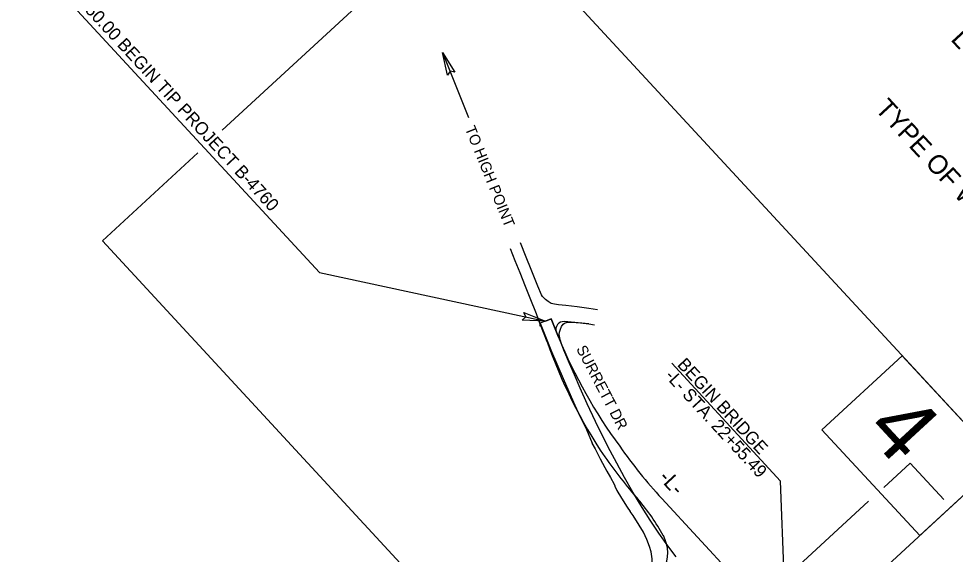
# Model space of a CAD drawing. Extents: x 1695041 to 1706254, y 786537 to 798223.
# Drawn here: x 1701995 to 1703837, y 795222 to 796276 of the extents above; entities that cross this region are included whole.
import ezdxf

# ---------------------------------------------------------------- set-up
doc = ezdxf.new("R2010")
doc.units = 0
for name, color, linetype in [('Default', 7, 'Continuous'), ('Old_Level_1', 7, 'Continuous'), ('Old_Level_3', 7, 'Continuous'), ('Old_Level_47', 7, 'Continuous'), ('Prop EOT', 7, 'Continuous'), ('Prop Terminator CELL', 7, 'Continuous'), ('Sheet Data Field CELL', 7, 'Continuous'), ('Sheet Title CELL', 7, 'Continuous')]:
    doc.layers.add(name, color=color, linetype=linetype)

msp = doc.modelspace()

# ---------------------------------------------------------------- linework, layer by layer
at = {"layer": 'Default'}
for p, q in [((1703042.2, 795685.9), (1703031.1, 795681.4)), ((1703052.8, 795659.7), (1703042.2, 795685.9)), ((1703031.1, 795681.4), (1703020, 795676.9)), ((1703020, 795676.9), (1703034.3, 795640.3)), ((1703056.9, 795649.4), (1703052.8, 795659.7)), ((1703279.5, 795598.4), (1703493.6, 795366.4)), ((1703449.8, 795126.4), (1703259.9, 795332.1))]:
    msp.add_line(p, q, dxfattribs=at)
for points in [[(1702347.2, 796012.7), (1702159.6, 795839.5), (1703188.6, 794724.8), (1703925.1, 795404.6), (1702896.1, 796519.3), (1702395.5, 796057.2)], [(1703147.7, 795414.2), (1703147.7, 795414.2)], [(1703814.8, 795329.9), (1703748.3, 795401.9), (1703696.3, 795353.9)], [(1703666.7, 795326.6), (1703127, 794828.4)]]:
    msp.add_lwpolyline(points, dxfattribs=at)
msp.add_lwpolyline([(1703925.1, 795404.6), (1703732.6, 795613), (1703574.9, 795467.4), (1703767.3, 795259)], close=True, dxfattribs=at)
for centre, radius, start, end in [((1703979, 796025.2), 995.7, 202.1738, 216.3622), ((1703995.4, 795980.9), 1019.7, 199.5127, 213.7658), ((1703981.5, 795998.2), 982, 215.0107, 222.7091), ((1703981.5, 795998.2), 1018, 215.0107, 221.0304), ((1702911.8, 795067.4), 400, 28.6224, 41.0304), ((1703201.5, 795225.4), 70, 332.0106, 28.6224)]:
    msp.add_arc(centre, radius, start, end, dxfattribs=at)
at = {"layer": 'Old_Level_1'}
for q in [(1701987.7, 796425.6), (1703031.1, 795681.4)]:
    msp.add_line((1702586.7, 795776.6), q, dxfattribs=at)
at = {"layer": 'Old_Level_3'}
for points in [[(1703031.2, 795723.7), (1703027.9, 795726.9), (1703025.2, 795729.7), (1703023.2, 795732.7), (1703016.2, 795749.9), (1703002.9, 795782.7), (1702993.3, 795807), (1702982, 795835.3)], [(1702961.6, 795824.1), (1702971.1, 795800.3), (1702980.5, 795777), (1702991.3, 795750), (1703000.4, 795727.3), (1703012.9, 795695.9), (1703020.1, 795676), (1703020.3, 795671.2)], [(1703133.3, 795703.3), (1703116.2, 795706.1), (1703093.3, 795709.6), (1703070.9, 795711.8), (1703056.6, 795713.1), (1703048.6, 795714.4), (1703042.6, 795716.1), (1703036.1, 795720.1), (1703031.2, 795723.7)], [(1703020.6, 795677.3), (1703034, 795644.2), (1703043.3, 795621.6), (1703053.5, 795597.1), (1703065.6, 795568.5), (1703077.1, 795542.4), (1703089, 795515.7), (1703099, 795493.8), (1703111.5, 795467.6), (1703122.7, 795441.2)], [(1703058.1, 795655), (1703058.6, 795659.7), (1703060.4, 795665.6), (1703062.7, 795670.3), (1703066.2, 795674.9), (1703068.6, 795677.4), (1703074.4, 795679.2), (1703083.1, 795679), (1703100.1, 795678.1), (1703116.2, 795676.1), (1703127.8, 795673.9)], [(1703288.1, 795217.4), (1703271.7, 795238.9), (1703254.2, 795263.5), (1703237.1, 795289.4), (1703221.3, 795314.1), (1703203, 795344.6), (1703186.3, 795373.7), (1703171.3, 795401.4), (1703158.1, 795425.6), (1703144.4, 795452.8), (1703129.6, 795483.4), (1703113, 795518.5), (1703099.4, 795549.5), (1703088.2, 795575.5), (1703078.5, 795597.8), (1703067.4, 795624.2), (1703061.9, 795638.3), (1703060.5, 795643.2), (1703059.3, 795648.1), (1703058.1, 795655)], [(1703122.6, 795441.2), (1703129, 795429.6), (1703138.9, 795410.4), (1703148, 795393.1), (1703151.9, 795385.9)], [(1703151.9, 795385.9), (1703158.7, 795373.2), (1703166, 795360.2), (1703167.4, 795357.3), (1703167.4, 795356.6)], [(1703167.4, 795356.6), (1703171.7, 795348.1), (1703180.9, 795332.8), (1703191.9, 795315), (1703197.6, 795306.6)], [(1703145.6, 795042.7), (1703159.4, 795057.7), (1703176.4, 795076.1), (1703190.4, 795091.1), (1703201.5, 795103.1), (1703210.6, 795113.4), (1703216.4, 795121.4), (1703222, 795130.2), (1703227.5, 795140.7), (1703231.4, 795152.1), (1703236.1, 795169.3), (1703239.6, 795184.4), (1703240.7, 795197.8), (1703240.8, 795213.5), (1703238.9, 795226.9), (1703235.9, 795237.7), (1703230.6, 795251.2), (1703223.9, 795265.8), (1703215.6, 795279.8), (1703203.6, 795298.5), (1703197.6, 795306.6)]]:
    msp.add_lwpolyline(points, dxfattribs=at)
at = {"layer": 'Old_Level_47'}
msp.add_line((1702828.7, 796210.1), (1702879.9, 796081.9), dxfattribs=at)
at = {"layer": 'Prop EOT'}
for p, q in [((1703031.1, 795681.4), (1703042.2, 795685.9)), ((1703042.2, 795685.9), (1703056.9, 795649.4)), ((1703031.1, 795681.4), (1703020, 795676.9)), ((1703034.3, 795640.3), (1703020, 795676.9)), ((1703116.2, 795676.1), (1703068, 795680.3)), ((1703259.9, 795332.1), (1703737.1, 794815.1))]:
    msp.add_line(p, q, dxfattribs=at)
for centre, radius, start, end in [((1703066.7, 795665.3), 15, 85.025, 201.9624), ((1703979, 796025.2), 995.7, 202.1738, 216.3622), ((1703995.4, 795980.9), 1019.7, 199.5127, 213.7658), ((1703981.5, 795998.2), 982, 215.0107, 222.7091), ((1703981.5, 795998.2), 1018, 215.0107, 221.0304), ((1702911.8, 795067.4), 400, 28.6224, 41.0304), ((1703201.5, 795225.4), 70, 332.0106, 28.6224)]:
    msp.add_arc(centre, radius, start, end, dxfattribs=at)
at = {"layer": 'Prop Terminator CELL'}
for points in [[(1702838.2, 796165.4), (1702828.7, 796210.1), (1702852.9, 796171), (1702843.4, 796173.4)], [(1702988.7, 795698.4), (1703031.1, 795681.4), (1702985.2, 795683), (1702992.5, 795689.7)]]:
    msp.add_lwpolyline(points, close=True, dxfattribs=at)
at = {"layer": 'Sheet Title CELL'}
msp.add_line((1703505.6, 795039.4), (1703493.6, 795366.4), dxfattribs=at)

# ---------------------------------------------------------------- texts
at = {"layer": 'Default'}
msp.add_text('-L- STA. 14+50.00 BEGIN TIP PROJECT B-4760', height=25, rotation=312.7091, dxfattribs=at).set_placement((1701995, 796432.4))
at = {"layer": 'Old_Level_47'}
for s, p in [('BEGIN BRIDGE', (1703288.8, 795594.4)), ('-L- STA. 22+55.49', (1703264.7, 795572.1))]:
    msp.add_text(s, height=25, rotation=312.7091, dxfattribs=at).set_placement(p)
at = {"layer": 'Sheet Data Field CELL'}
msp.add_text('       GUILFORD COUNTY       ', height=90, rotation=312.7091, dxfattribs=at).set_placement((1703526.2, 796800.7))
at = {"layer": 'Sheet Title CELL'}
for s, height, rotation, p in [('LOCATION: ', 37.5, 312.7091, (1703826.7, 796234.8)), ('TYPE OF WORK:', 37.5, 312.7091, (1703677.8, 796097.5)), ('TO HIGH POINT', 21.157, 292.0469, (1702872.3, 796060.4)), ('SURRETT DR', 21.16, 297.479, (1703091.1, 795626.8)), ('4', 128.4, 312.7091, (1703656.2, 795464.1)), ('-L- ', 30, 312.7091, (1703252.3, 795371.8))]:
    msp.add_text(s, height=height, rotation=rotation, dxfattribs=at).set_placement(p)

doc.saveas('drawing.dxf')
